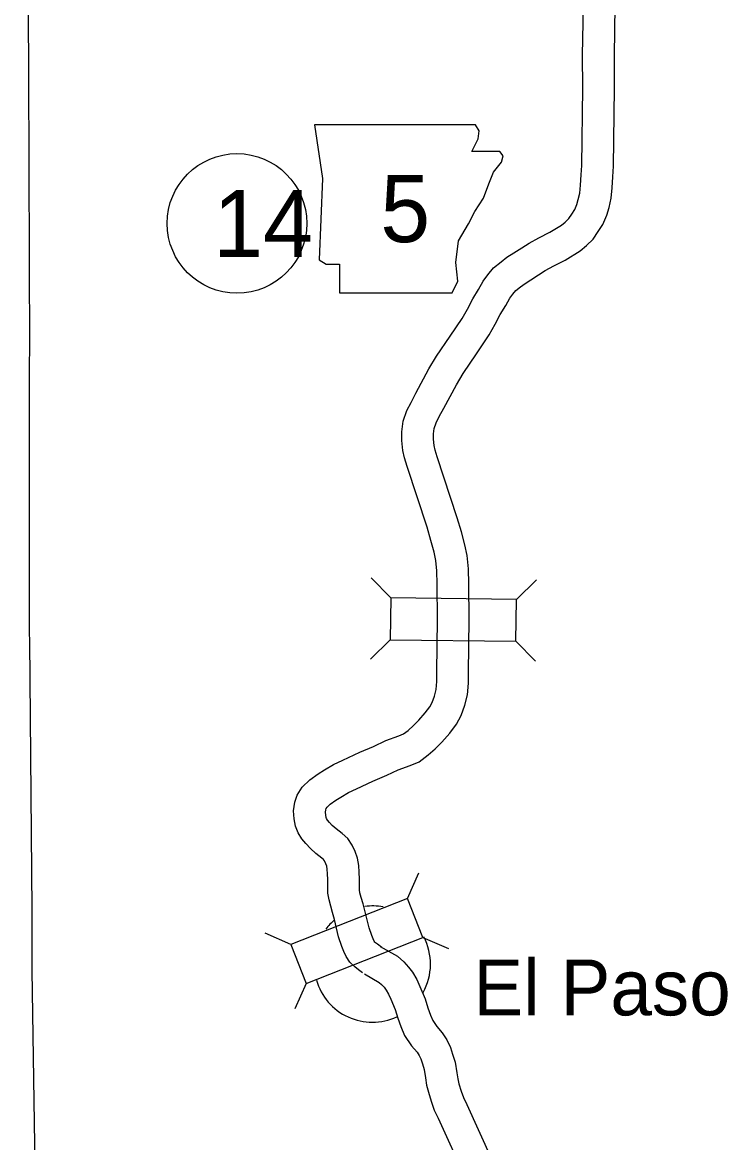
# Model space of a CAD drawing. Extents: x -939622 to -934222, y 1383701 to 1385301.
# Drawn here: x -936504.28 to -936484.27, y 1384466.5 to 1384498.28 of the extents above; entities that cross this region are included whole.
import ezdxf

# ---------------------------------------------------------------- set-up
doc = ezdxf.new("R2010")
doc.units = 0
for name, color, linetype in [('10', 7, 'Continuous'), ('2', 7, 'Continuous'), ('20', 7, 'Continuous'), ('21', 7, 'Continuous'), ('24', 7, 'Continuous'), ('27', 7, 'Continuous')]:
    doc.layers.add(name, color=color, linetype=linetype)

msp = doc.modelspace()

# ---------------------------------------------------------------- linework, layer by layer
at = {"layer": '10'}
for points in [[(-936494.626, 1384471.322), (-936494.742, 1384471.41), (-936494.851, 1384471.488), (-936494.987, 1384471.625), (-936495.089, 1384471.787), (-936495.156, 1384471.929), (-936495.211, 1384472.068), (-936495.309, 1384472.345), (-936495.424, 1384472.833), (-936495.476, 1384473.029), (-936495.532, 1384473.213), (-936495.579, 1384473.392), (-936495.617, 1384473.585), (-936495.616, 1384473.777), (-936495.615, 1384473.967), (-936495.621, 1384474.128), (-936495.631, 1384474.262), (-936495.645, 1384474.347), (-936495.667, 1384474.41), (-936495.708, 1384474.494), (-936495.738, 1384474.539), (-936495.781, 1384474.578), (-936495.95, 1384474.708), (-936496.107, 1384474.848), (-936496.241, 1384474.986), (-936496.354, 1384475.123), (-936496.458, 1384475.292), (-936496.534, 1384475.482), (-936496.568, 1384475.686), (-936496.586, 1384475.915), (-936496.548, 1384476.158), (-936496.479, 1384476.364), (-936496.343, 1384476.587), (-936496.126, 1384476.796), (-936495.89, 1384476.968), (-936495.706, 1384477.079), (-936495.448, 1384477.229), (-936495.188, 1384477.353), (-936494.706, 1384477.579), (-936494.316, 1384477.746), (-936493.966, 1384477.916), (-936493.598, 1384478.046), (-936493.47, 1384478.098), (-936493.338, 1384478.199), (-936493.183, 1384478.336), (-936493.033, 1384478.485), (-936492.848, 1384478.696), (-936492.72, 1384478.863), (-936492.655, 1384478.985), (-936492.587, 1384479.172), (-936492.543, 1384479.358), (-936492.52, 1384479.584), (-936492.519, 1384479.847), (-936492.501, 1384481.342), (-936492.512, 1384482.343), (-936492.518, 1384482.728), (-936492.548, 1384483.016), (-936492.598, 1384483.25), (-936492.689, 1384483.588), (-936492.799, 1384483.962), (-936493.366, 1384485.687), (-936493.438, 1384485.926), (-936493.483, 1384486.138), (-936493.512, 1384486.421), (-936493.511, 1384486.672), (-936493.474, 1384486.975), (-936493.367, 1384487.272), (-936493.253, 1384487.504), (-936493.118, 1384487.764), (-936492.75, 1384488.451), (-936492.531, 1384488.815), (-936492.138, 1384489.382), (-936491.803, 1384489.887), (-936491.654, 1384490.15), (-936491.503, 1384490.438), (-936491.34, 1384490.707), (-936491.206, 1384490.942), (-936491.078, 1384491.123), (-936490.91, 1384491.324), (-936490.7, 1384491.49), (-936490.535, 1384491.619), (-936490.332, 1384491.746), (-936490.111, 1384491.888), (-936489.902, 1384492.016), (-936489.628, 1384492.173), (-936489.318, 1384492.33), (-936488.983, 1384492.534), (-936488.883, 1384492.618), (-936488.777, 1384492.721), (-936488.688, 1384492.848), (-936488.607, 1384492.977), (-936488.545, 1384493.115), (-936488.507, 1384493.256), (-936488.464, 1384493.441), (-936488.444, 1384493.663), (-936488.424, 1384493.958), (-936488.411, 1384494.228), (-936488.381, 1384496.414), (-936488.384, 1384497.355), (-936488.362, 1384498.748)], [(-936494.082, 1384472.039), (-936494.207, 1384472.134), (-936494.265, 1384472.175), (-936494.278, 1384472.189), (-936494.298, 1384472.221), (-936494.329, 1384472.286), (-936494.367, 1384472.383), (-936494.444, 1384472.599), (-936494.551, 1384473.053), (-936494.611, 1384473.274), (-936494.665, 1384473.458), (-936494.702, 1384473.594), (-936494.717, 1384473.671), (-936494.716, 1384473.773), (-936494.715, 1384473.981), (-936494.722, 1384474.179), (-936494.737, 1384474.369), (-936494.77, 1384474.571), (-936494.835, 1384474.758), (-936494.924, 1384474.939), (-936495.048, 1384475.129), (-936495.204, 1384475.269), (-936495.375, 1384475.402), (-936495.485, 1384475.499), (-936495.57, 1384475.587), (-936495.621, 1384475.648), (-936495.651, 1384475.697), (-936495.662, 1384475.725), (-936495.674, 1384475.796), (-936495.68, 1384475.879), (-936495.67, 1384475.945), (-936495.658, 1384475.983), (-936495.636, 1384476.018), (-936495.546, 1384476.104), (-936495.39, 1384476.218), (-936495.246, 1384476.306), (-936495.028, 1384476.432), (-936494.804, 1384476.539), (-936494.337, 1384476.758), (-936493.941, 1384476.927), (-936493.619, 1384477.084), (-936493.276, 1384477.205), (-936493.019, 1384477.311), (-936492.767, 1384477.502), (-936492.567, 1384477.679), (-936492.377, 1384477.868), (-936492.153, 1384478.124), (-936491.961, 1384478.373), (-936491.83, 1384478.619), (-936491.723, 1384478.914), (-936491.654, 1384479.208), (-936491.62, 1384479.537), (-936491.619, 1384479.84), (-936491.601, 1384481.341), (-936491.612, 1384482.355), (-936491.619, 1384482.781), (-936491.657, 1384483.158), (-936491.723, 1384483.461), (-936491.822, 1384483.831), (-936491.939, 1384484.23), (-936492.507, 1384485.957), (-936492.565, 1384486.151), (-936492.593, 1384486.279), (-936492.612, 1384486.464), (-936492.611, 1384486.615), (-936492.593, 1384486.766), (-936492.537, 1384486.921), (-936492.45, 1384487.099), (-936492.322, 1384487.343), (-936491.967, 1384488.006), (-936491.775, 1384488.326), (-936491.393, 1384488.877), (-936491.036, 1384489.416), (-936490.864, 1384489.719), (-936490.719, 1384489.996), (-936490.565, 1384490.25), (-936490.446, 1384490.457), (-936490.363, 1384490.574), (-936490.278, 1384490.677), (-936490.144, 1384490.783), (-936490.018, 1384490.881), (-936489.851, 1384490.985), (-936489.633, 1384491.125), (-936489.443, 1384491.241), (-936489.2, 1384491.381), (-936488.88, 1384491.543), (-936488.458, 1384491.801), (-936488.279, 1384491.95), (-936488.089, 1384492.135), (-936487.939, 1384492.349), (-936487.811, 1384492.552), (-936487.695, 1384492.812), (-936487.634, 1384493.036), (-936487.573, 1384493.299), (-936487.547, 1384493.591), (-936487.525, 1384493.905), (-936487.511, 1384494.201), (-936487.481, 1384496.409), (-936487.484, 1384497.35), (-936487.462, 1384498.749)], [(-936494.13, 1384472.071), (-936493.64, 1384471.79), (-936493.454, 1384471.636), (-936493.32, 1384471.479), (-936493.207, 1384471.335), (-936493.088, 1384471.128), (-936492.999, 1384470.929), (-936492.856, 1384470.584), (-936492.774, 1384470.325), (-936492.699, 1384470.12), (-936492.635, 1384469.965), (-936492.522, 1384469.796), (-936492.367, 1384469.618), (-936492.233, 1384469.418), (-936492.137, 1384469.206), (-936492.072, 1384469.01), (-936492.005, 1384468.784), (-936491.953, 1384468.485), (-936491.928, 1384468.309), (-936491.893, 1384468.175), (-936491.829, 1384467.962), (-936491.763, 1384467.78), (-936491.666, 1384467.583), (-936489.967, 1384463.833)], [(-936494.577, 1384471.29), (-936494.154, 1384471.047), (-936494.088, 1384470.993), (-936494.017, 1384470.909), (-936493.955, 1384470.831), (-936493.891, 1384470.718), (-936493.825, 1384470.573), (-936493.703, 1384470.276), (-936493.626, 1384470.034), (-936493.538, 1384469.794), (-936493.433, 1384469.539), (-936493.239, 1384469.248), (-936493.083, 1384469.069), (-936493.022, 1384468.979), (-936492.976, 1384468.877), (-936492.93, 1384468.74), (-936492.883, 1384468.578), (-936492.842, 1384468.345), (-936492.812, 1384468.132), (-936492.76, 1384467.931), (-936492.684, 1384467.679), (-936492.593, 1384467.427), (-936492.479, 1384467.198), (-936490.953, 1384463.83)]]:
    msp.add_lwpolyline(points, dxfattribs=at)
at = {"layer": '2'}
for points in [[(-936504.277, 1384526.548), (-936504.267, 1384521.26), (-936504.265, 1384521.113), (-936504.227, 1384513.193), (-936504.219, 1384513.067), (-936504.174, 1384507.099), (-936504.14, 1384506.114), (-936504.132, 1384505.847), (-936504.131, 1384505.723), (-936504.143, 1384505.663), (-936504.153, 1384505.593), (-936504.169, 1384505.481), (-936504.171, 1384505.274), (-936504.173, 1384504.323), (-936504.109, 1384497.198), (-936504.103, 1384496.813), (-936504.077, 1384488.986), (-936504.082, 1384488.625), (-936504.089, 1384480.962), (-936504.072, 1384480.743), (-936504.009, 1384473.107), (-936504.006, 1384472.968), (-936504.006, 1384471.389)], [(-936504.006, 1384471.389), (-936503.911, 1384465.227), (-936503.91, 1384465.107), (-936503.891, 1384461.209)]]:
    msp.add_lwpolyline(points, dxfattribs=at)
at = {"layer": '20'}
for p, q in [((-936493.826, 1384481.957), (-936494.379, 1384482.524)), ((-936490.262, 1384481.914), (-936489.695, 1384482.468)), ((-936493.84, 1384480.769), (-936494.406, 1384480.216)), ((-936490.276, 1384480.726), (-936489.723, 1384480.16)), ((-936493.348, 1384473.43), (-936493.031, 1384474.156)), ((-936496.665, 1384472.127), (-936497.391, 1384472.444)), ((-936492.913, 1384472.324), (-936492.187, 1384472.008)), ((-936496.23, 1384471.021), (-936496.547, 1384470.295))]:
    msp.add_line(p, q, dxfattribs=at)
for points in [[(-936493.84, 1384480.769), (-936490.276, 1384480.726), (-936490.262, 1384481.914), (-936493.826, 1384481.957)], [(-936496.23, 1384471.021), (-936492.913, 1384472.324), (-936493.348, 1384473.43), (-936496.665, 1384472.127)]]:
    msp.add_lwpolyline(points, close=True, dxfattribs=at)
at = {"layer": '21'}
msp.add_lwpolyline([(-936495.989, 1384495.382), (-936495.761, 1384493.859), (-936495.862, 1384491.55), (-936495.659, 1384491.423), (-936495.279, 1384491.423), (-936495.279, 1384490.611), (-936492.081, 1384490.611), (-936491.929, 1384490.941), (-936491.98, 1384491.474), (-936491.904, 1384492.083), (-936491.624, 1384492.565), (-936491.447, 1384492.92), (-936491.193, 1384493.301), (-936491.041, 1384493.707), (-936490.914, 1384494.037), (-936490.685, 1384494.316), (-936490.635, 1384494.494), (-936490.736, 1384494.621), (-936491.523, 1384494.621), (-936491.345, 1384494.976), (-936491.32, 1384495.204), (-936491.425, 1384495.38)], close=True, dxfattribs=at)
at = {"layer": '24'}
for start, end in [(79.2319, 97.5239), (130.4861, 143.0591), (330.7388, 27.9699), (195.9936, 294.8001)]:
    msp.add_arc((-936494.35, 1384471.568), 1.65, start, end, dxfattribs=at)
at = {"layer": '27'}
msp.add_circle((-936498.19, 1384492.581), 1.98, dxfattribs=at)

# ---------------------------------------------------------------- texts
at = {"layer": '21'}
msp.add_text('5', height=1.901, dxfattribs=at).set_placement((-936494.123, 1384492.05))
at = {"layer": '24'}
msp.add_text('El Paso', height=1.584, dxfattribs=at).set_placement((-936491.483, 1384470.113))
at = {"layer": '27'}
msp.add_text('14', height=1.9008, dxfattribs=at).set_placement((-936498.863, 1384491.63))

doc.saveas('drawing.dxf')
